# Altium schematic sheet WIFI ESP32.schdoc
size 325 x 221 mm
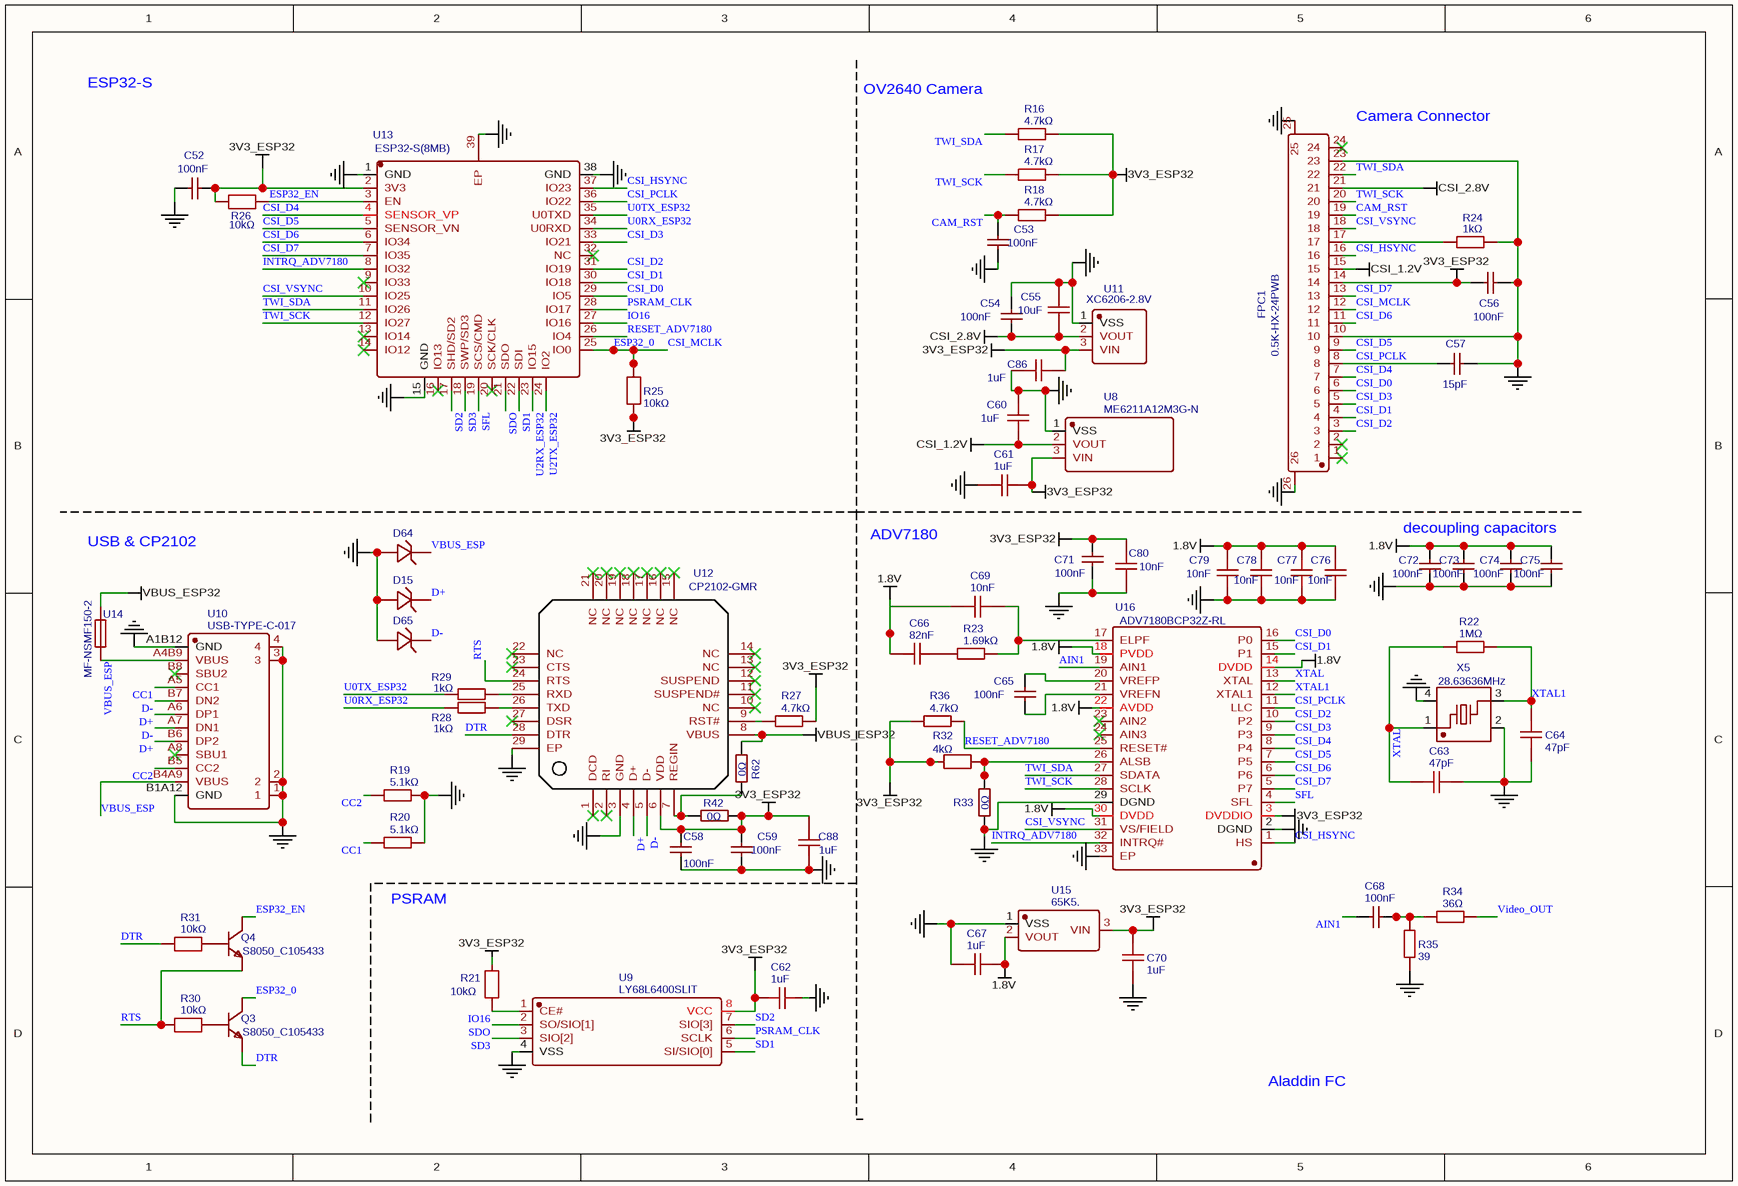
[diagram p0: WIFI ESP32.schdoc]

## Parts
C52  100nF  [C0805]
C53  100nF  [C0805]
C54  100nF  [C0805]
C55  10uF  [C0805]
C56  100nF  [C0805]
C57  15pF  [C0805]
C58  100nF  [C0805]
C59  100nF  [C0805]
C60  1uF  [C0805]
C61  1uF  [C0805]
C62  1uF  [C0805]
C63  47pF  [C0805]
C64  47pF  [C0805]
C65  100nF  [C0805]
C66  82nF  [C0805]
C67  1uF  [C0805]
C68  100nF  [C0805]
C69  10nF  [C0805]
C70  1uF  [C0805]
C71  100nF  [C0805]
C72  100nF  [C0805]
C73  100nF  [C0805]
C74  100nF  [C0805]
C75  100nF  [C0805]
C76  10nF  [C0805]
C77  10nF  [C0805]
C78  10nF  [C0805]
C79  10nF  [C0805]
C80  10nF  [C0805]
C86  1uF  [C0805]
C88  1uF  [C0805]
D15  ESD9X5V-2/TR  [FBP-02C_L1.0-W0.6-RD]  (value not drawn)
D64  ESD9X5V-2/TR  [FBP-02C_L1.0-W0.6-RD]  (value not drawn)
D65  ESD9X5V-2/TR  [FBP-02C_L1.0-W0.6-RD]  (value not drawn)
FPC1  0.5K-HX-24PWB  [FPC-SMD_24P-P0.50_HDGC_0.5K-HX-24PWB]
Q3  S8050_C105433  [SOT-23-3_L2.9-W1.6-P1.90-LS2.8-BR]
Q4  S8050_C105433  [SOT-23-3_L2.9-W1.6-P1.90-LS2.8-BR]
R16  4.7kΩ  [R0805]
R17  4.7kΩ  [R0805]
R18  4.7kΩ  [R0805]
R19  5.1kΩ  [R0402]
R20  5.1kΩ  [R0402]
R21  10kΩ  [R0805]
R22  1MΩ  [R0805]
R23  1.69kΩ  [R0805]
R24  1kΩ  [R0805]
R25  10kΩ  [R0805]
R26  10kΩ  [R0805]
R27  4.7kΩ  [R0805]
R28  1kΩ  [R0805]
R29  1kΩ  [R0805]
R30  10kΩ  [R0805]
R31  10kΩ  [R0805]
R32  4kΩ  [R0805]
R33  0Ω  [R0805]
R34  36Ω  [R0805]
R35  39  [R0805]
R36  4.7kΩ  [R0805]
R42  0Ω  [R0805]
R62  0Ω  [R0805]
U8  ME6211A12M3G-N  [SOT-23-3_L2.9-W1.6-P1.90-LS2.8-BR]
U9  LY68L6400SLIT  [SOP-8_L4.9-W3.9-P1.27-LS6.0-BL]
U10  USB-TYPE-C-017  [USB-TYPE-C-SMD_C9900008089_ALA1]
U11  XC6206-2.8V  [SOT-23-3_L2.9-W1.6-P1.90-LS2.8-BR]
U12  CP2102-GMR  [WQFN-28_L5.0-W5.0-P0.50-BL-EP3.2]
U13  ESP32-S(8MB)  [WIRELM-SMD_ESP32-S]
U14  MF-NSMF150-2  [F1206]
U15  65K5.  [SOT-23-3_L2.9-W1.3-P1.90-LS2.4-BR]
U16  ADV7180BCP32Z-RL  [LFCSP-32_L5.0-W5.0-P0.50-BL-EP3.6]
X5  28.63636MHz  [CRYSTAL-SMD_4P-L3.2-W2.5-BL]

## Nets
1.8V: C66.1 C67.2 C69.1 C72.1 C73.1 C74.1 C75.1 C76.2 C77.2 C78.1 C79.2 U15.2(VOUT) U16.14(DVDD) U16.18(PVDD) U16.22(AVDD) U16.30(DVDD)
3V3_ESP32: C52.1 C56.2 C58.2 C59.2 C61.2 C62.1 C70.1 C71.1 C80.2 C86.2 C88.2 FPC1.14 R16.2 R17.2 R18.2 R21.2 R25.1 R26.1 R27.2 R32.1 R36.1 R42.1 U8.3(VIN) U9.8(VCC) U11.3(VIN) U12.6(VDD) U13.2(3V3) U15.3(VIN) U16.3(DVDDIO)
CSI_1.2V: C60.2 FPC1.15 U8.2(VOUT)
CSI_2.8V: C54.2 C55.1 FPC1.21 U11.2(VOUT)
GND: C52.2 C53.2 C54.1 C55.2 C56.1 C57.1 C58.1 C59.1 C60.1 C61.1 C62.2 C63.2 C64.1 C67.1 C70.2 C71.2 C72.2 C73.2 C74.2 C75.2 C76.1 C77.1 C78.2 C79.1 C80.1 C86.1 C88.1 D15.2 D64.2 D65.2 FPC1.10 FPC1.23 FPC1.25 FPC1.26 R19.2 R20.2 R24.2 R33.1 R35.1 U8.1(VSS) U9.4(VSS) U10.1 U10.2 U10.3 U10.4 U10.A1B12(GND) U10.B1A12(GND) U11.1(VSS) U12.3(GND) U12.29(EP) U13.1(GND) U13.15(GND) U13.38(GND) U13.39(EP) U15.1(VSS) U16.2(DGND) U16.29(DGND) U16.33(EP) X5.2(GND) X5.4(GND)
VBUS_ESP32: R62.1 U12.8(VBUS) U14.2
AIN1: C68.1 U16.19(AIN1)
CAM_RST: C53.1 FPC1.19 R18.1
CC1: R20.1 U10.A5(CC1)
CC2: R19.1 U10.B5(CC2)
CSI_D0: FPC1.6 U13.29(IO5) U16.16(P0)
CSI_D1: FPC1.4 U13.30(IO18) U16.15(P1)
CSI_D2: FPC1.3 U13.31(IO19) U16.10(P2)
CSI_D3: FPC1.5 U13.33(IO21) U16.9(P3)
CSI_D4: FPC1.7 U13.4(SENSOR_VP) U16.8(P4)
CSI_D5: FPC1.9 U13.5(SENSOR_VN) U16.7(P5)
CSI_D6: FPC1.11 U13.6(IO34) U16.6(P6)
CSI_D7: FPC1.13 U13.7(IO35) U16.5(P7)
CSI_HSYNC: FPC1.16 U13.37(IO23) U16.1(HS)
CSI_MCLK: FPC1.12 Q3.3 R25.2 U13.25(IO0)  [also labelled ESP32_0]
CSI_PCLK: C57.2 FPC1.8 U13.36(IO22) U16.11(LLC)
CSI_VSYNC: FPC1.18 U13.10(IO25) U16.31(VS/FIELD)
D+: D15.1 U10.A6(DP1) U10.B6(DP2) U12.4(D+)
D-: D65.1 U10.A7(DN1) U10.B7(DN2) U12.5(D-)
DTR: Q3.2 R31.1 U12.28(DTR)
ESP32_EN: Q4.3 R26.2 U13.3(EN)
INTRQ_ADV7180: U13.8(IO32) U16.32(INTRQ#)
IO16: R21.1 U9.1(CE#) U13.27(IO16)
PSRAM_CLK: U9.6(SCLK) U13.28(IO17)
RESET_ADV7180: R36.2 U13.26(IO4) U16.25(RESET#)
RTS: Q4.2 R30.1 U12.24(RTS)
SD1: U9.5(SI/SIO[0]) U13.22(SDI)
SD2: U9.7(SIO[3]) U13.17(SHD/SD2)
SD3: U9.3(SIO[2]) U13.18(SWP/SD3)
SDO: U9.2(SO/SIO[1]) U13.21(SDO)
SFL: U13.19(SCS/CMD) U16.4(SFL)
TWI_SCK: FPC1.20 R17.1 U13.12(IO27) U16.28(SCLK)
TWI_SDA: FPC1.22 R16.1 U13.11(IO26) U16.27(SDATA)
U0RX_ESP32: R28.1 U13.34(U0RXD)
U0TX_ESP32: R29.1 U13.35(U0TXD)
U2RX_ESP32: U13.23(IO15)
U2TX_ESP32: U13.24(IO2)
VBUS_ESP: D64.1 U10.A4B9(VBUS) U10.B4A9(VBUS) U14.1
Video_OUT: R34.2
XTAL: C63.1 R22.2 U16.13(XTAL) X5.1
XTAL1: C64.2 R22.1 U16.12(XTAL1) X5.3
NetC65_1: C65.1 U16.20(VREFP)
NetC65_2: C65.2 U16.21(VREFN)
NetC66_2: C66.2 R23.1
NetC68_2: C68.2 R34.1 R35.2
NetC69_2: C69.2 R23.2 U16.17(ELPF)
NetFPC1_17: FPC1.17 R24.1
NetQ3_1: Q3.1 R30.2
NetQ4_1: Q4.1 R31.2
NetR27_1: R27.1 U12.9(RST#)
NetR28_2: R28.2 U12.26(TXD)
NetR29_2: R29.2 U12.25(RXD)
NetR32_2: R32.2 R33.2 U16.26(ALSB)
NetR42_2: R42.2 R62.2 U12.7(REGIN)

Not connected (* = marked no-connect by the designer): FPC1 1* 2* 24*; U10 A8(SBU1)* B8(SBU2)*; U12 1(DCD)* 2(RI)* 10(NC)* 11(SUSPEND#)* 12(SUSPEND)* 13(NC)* 14(NC)* 15(NC)* 16(NC)* 17(NC)* 18(NC)* 19(NC)* 20(NC)* 21(NC)* 22(NC)* 23(CTS)* 27(DSR)*; U13 9(IO33)* 13(IO14)* 14(IO12)* 16(IO13)* 20(SCK/CLK)* 32(NC)*; U16 23(AIN2)* 24(AIN3)*

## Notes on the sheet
- ESP32-S
- OV2640 Camera
- (near FPC1) Camera Connector
- decoupling capacitors
- USB & CP2102
- ADV7180
- (near R20) PSRAM
- Aladdin FC

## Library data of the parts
C52-C54 C56 C58 C59 C65 C68 C71-C75 = 100nF: BOM_Manufacturer Part: CL21B104KBCNNNC; BOM_Manufacturer: SAMSUNG; nameAlias: Capacitance
C55 = 10uF: BOM_Manufacturer: Taiyo Yuden; BOM_Manufacturer Part: TMK212BBJ106KGHT; nameAlias: Capacitance; Contributor: LCSC
C57 = 15pF: BOM_Manufacturer: FH; BOM_Manufacturer Part: 0805CG150J500NT; nameAlias: Capacitance
C60-C62 C67 C70 C86 C88 = 1uF: BOM_Manufacturer: Taiyo Yuden; BOM_Manufacturer Part: UMK212BJ105KG-T; nameAlias: Capacitance; Contributor: LCSC
C63 C64 = 47pF: BOM_Manufacturer: muRata(村田); BOM_Manufacturer Part: GCM21A5C2E470JX01D; Contributor: lcsc
C66 = 82nF: BOM_Manufacturer: YAGEO; BOM_Manufacturer Part: CC0805JRX7R9BB823; nameAlias: Capacitance; Contributor: LCSC
C69 C76-C80 = 10nF: BOM_Manufacturer: YAGEO; BOM_Manufacturer Part: CC0805KRX7R9BB103; nameAlias: Capacitance
D15 D64 D65 = ESD9X5V-2/TR: BOM_Manufacturer: Will Semicon; Contributor: LCSC
FPC1 = 0.5K-HX-24PWB: BOM_Manufacturer: HDGC(华德共创); Contributor: LCSC
Q3 Q4 = S8050_C105433: BOM_Manufacturer: CJ; BOM_Manufacturer Part: S8050
R16-R18 R27 R36 = 4.7kΩ: BOM_Manufacturer: Tyohm; BOM_Manufacturer Part: RMC08054.7K1%N; Resistance (Ohms): 4.7K; nameAlias: Resistance; Contributor: LCSC
R19 R20 = 5.1kΩ: BOM_Manufacturer: Tyohm; BOM_Manufacturer Part: RMC04025.1K5%N; Resistance (Ohms): 5.1K; nameAlias: Resistance; Contributor: LCSC
R21 R25 R26 R30 R31 = 10kΩ: BOM_Manufacturer: Viking Tech; BOM_Manufacturer Part: ARG05BTC1002; Resistance (Ohms): 10K; nameAlias: Resistance; Contributor: LCSC
R22 = 1MΩ: BOM_Manufacturer: Viking Tech; BOM_Manufacturer Part: AR05BTCW1004; Resistance (Ohms): 1M; nameAlias: Resistance; Contributor: LCSC
R23 = 1.69kΩ: BOM_Manufacturer: Viking Tech; BOM_Manufacturer Part: ARG05FTC1691; Resistance (Ohms): 1.69K; nameAlias: Resistance; Contributor: LCSC
R24 R28 R29 = 1kΩ: BOM_Manufacturer: Viking Tech; BOM_Manufacturer Part: ARG05BTC1001; Resistance (Ohms): 1K; nameAlias: Resistance; Contributor: LCSC
R32 = 4kΩ: BOM_Manufacturer: 光颉(Viking); BOM_Manufacturer Part: ARG05FTC4001N; Contributor: LCSC; nameAlias: Resistance
R33 R42 R62 = 0Ω: BOM_Manufacturer: UniOhm; BOM_Manufacturer Part: 0805W8F0000T5E; nameAlias: Resistance; Resistance (Ohms): 0
R34 = 36Ω: BOM_Manufacturer: ResistorToday; BOM_Manufacturer Part: AECR0805F36R0K9; Resistance (Ohms): 36; nameAlias: Resistance; Contributor: LCSC
R35 = 39: BOM_Manufacturer: YAGEO; BOM_Manufacturer Part: AC0805JR-0739RL; nameAlias: Resistance (Ohms); Contributor: LCSC; Resistance: 39Ω
U8 = ME6211A12M3G-N: BOM_Manufacturer: Nanjing Micro One Elec; Contributor: LCSC
U9 = LY68L6400SLIT: BOM_Manufacturer: Lyontek Inc.; Contributor: LCSC
U10 = USB-TYPE-C-017: BOM_Manufacturer: DEALON(德艺隆); Contributor: lcsc
U11 = XC6206-2.8V: BOM_Manufacturer: YONGYUTAI(永裕泰); Contributor: LCSC
U12 = CP2102-GMR: BOM_Manufacturer: SILICON LABS
U13 = ESP32-S(8MB): BOM_Manufacturer: Ai-Thinker(安信可); Contributor: lcsc
U14 = MF-NSMF150-2: BOM_Manufacturer: BOURNS
U15 = 65K5.: BOM_Manufacturer: Shenzhen Fuman Elec; Contributor: LCSC
U16 = ADV7180BCP32Z-RL: BOM_Manufacturer: Analog Devices; Contributor: LCSC
X5 = 28.63636MHz: BOM_Manufacturer: HD; BOM_Manufacturer Part: 7B028636R01; nameAlias: Frequency; Contributor: LCSC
